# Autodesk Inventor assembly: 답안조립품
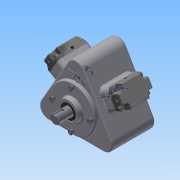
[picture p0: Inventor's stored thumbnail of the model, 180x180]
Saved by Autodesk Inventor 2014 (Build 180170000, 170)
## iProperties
Created: 2015-06
Part Number: 답안조립품
Document SubType Name: Assembly
Designer: Administrator
Mass: 5318.59 g
Surface Area: 2414.94 cm^2
Volume: 1564.62 cm^3
Density: 3.39929 g/cm^3
Author: Administrator
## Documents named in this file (20)
- C:\Documents and Settings\MYHOME\바탕 화면\350605V1041\답안조립품.iam
- C:\Documents and Settings\MYHOME\바탕 화면\350605V1041\본체.ipt
- C:\Documents and Settings\MYHOME\바탕 화면\350605V1041\베어링 NA 4904.ipt
- 베어링 NA 4904.ipt
- C:\Documents and Settings\MYHOME\바탕 화면\350605V1041\편심축.ipt
- C:\Documents and Settings\MYHOME\바탕 화면\350605V1041\앞커버.ipt
- C:\Documents and Settings\MYHOME\바탕 화면\350605V1041\오일실.ipt
- 오일실.ipt
- C:\Documents and Settings\MYHOME\바탕 화면\350605V1041\M6x0.7x20.ipt
- M6x0.7x20.ipt
- C:\Documents and Settings\MYHOME\바탕 화면\350605V1041\부시.ipt
- C:\Documents and Settings\MYHOME\바탕 화면\350605V1041\슬라이드.ipt
- C:\Documents and Settings\MYHOME\바탕 화면\350605V1041\8-가변스프링.ipt
- C:\Documents and Settings\MYHOME\바탕 화면\350605V1041\11-가변스프링.ipt
- C:\Documents and Settings\MYHOME\바탕 화면\350605V1041\9-가변스프링.ipt
- C:\Documents and Settings\MYHOME\바탕 화면\350605V1041\10-가변스프링.ipt
- C:\Documents and Settings\MYHOME\바탕 화면\350605V1041\헤더커버.ipt
- 헤더커버.ipt
- C:\Documents and Settings\MYHOME\바탕 화면\350605V1041\M4x0.5x16.ipt
- M4x0.5x16.ipt
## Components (18 placed, 7 different names)
1. 8-가변스프링:1
2. 9-가변스프링:1
3. 10-가변스프링:1
4. 11-가변스프링:1
5. 헤더커버:1
6. 헤더커버:2
7. M4x0.5x16:1
8. M4x0.5x16:2
9. M4x0.5x16:3
10. M4x0.5x16:4
11. M4x0.5x16:5
12. M4x0.5x16:6
13. M4x0.5x16:7
14. M4x0.5x16:8
15. M6x0.7x20:1
16. M6x0.7x20:2
17. M6x0.7x20:3
18. M6x0.7x20:4
